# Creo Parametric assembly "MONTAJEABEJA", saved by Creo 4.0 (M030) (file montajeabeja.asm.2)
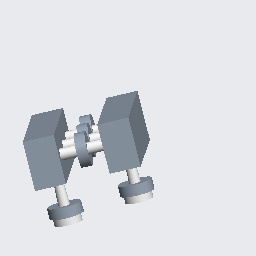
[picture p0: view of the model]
Units: millimeter Newton Second (mmNs); MM, TONNE, SECS

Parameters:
  MODELED_BY = "aj"

Created from: MMNS_ASM_DESIGN.ASM

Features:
  1. datum plane "ASM_RIGHT"
  2. datum plane "ASM_TOP"
  3. datum plane "ASM_FRONT"
  4. coordinate system
  5. component "LADOSUNIONESABEJA"
  6. component "EJECENTROABEJA"
  7. component "EJECENTROABEJA"
  8. component "EJECENTROABEJA"
  9. component "LADOSUNIONESABEJA"
  10. component "EJELATERALABEJA"
  11. component "EJELATERALABEJA"

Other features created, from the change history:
  component "LADOSUNIONESABEJA.PRT"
